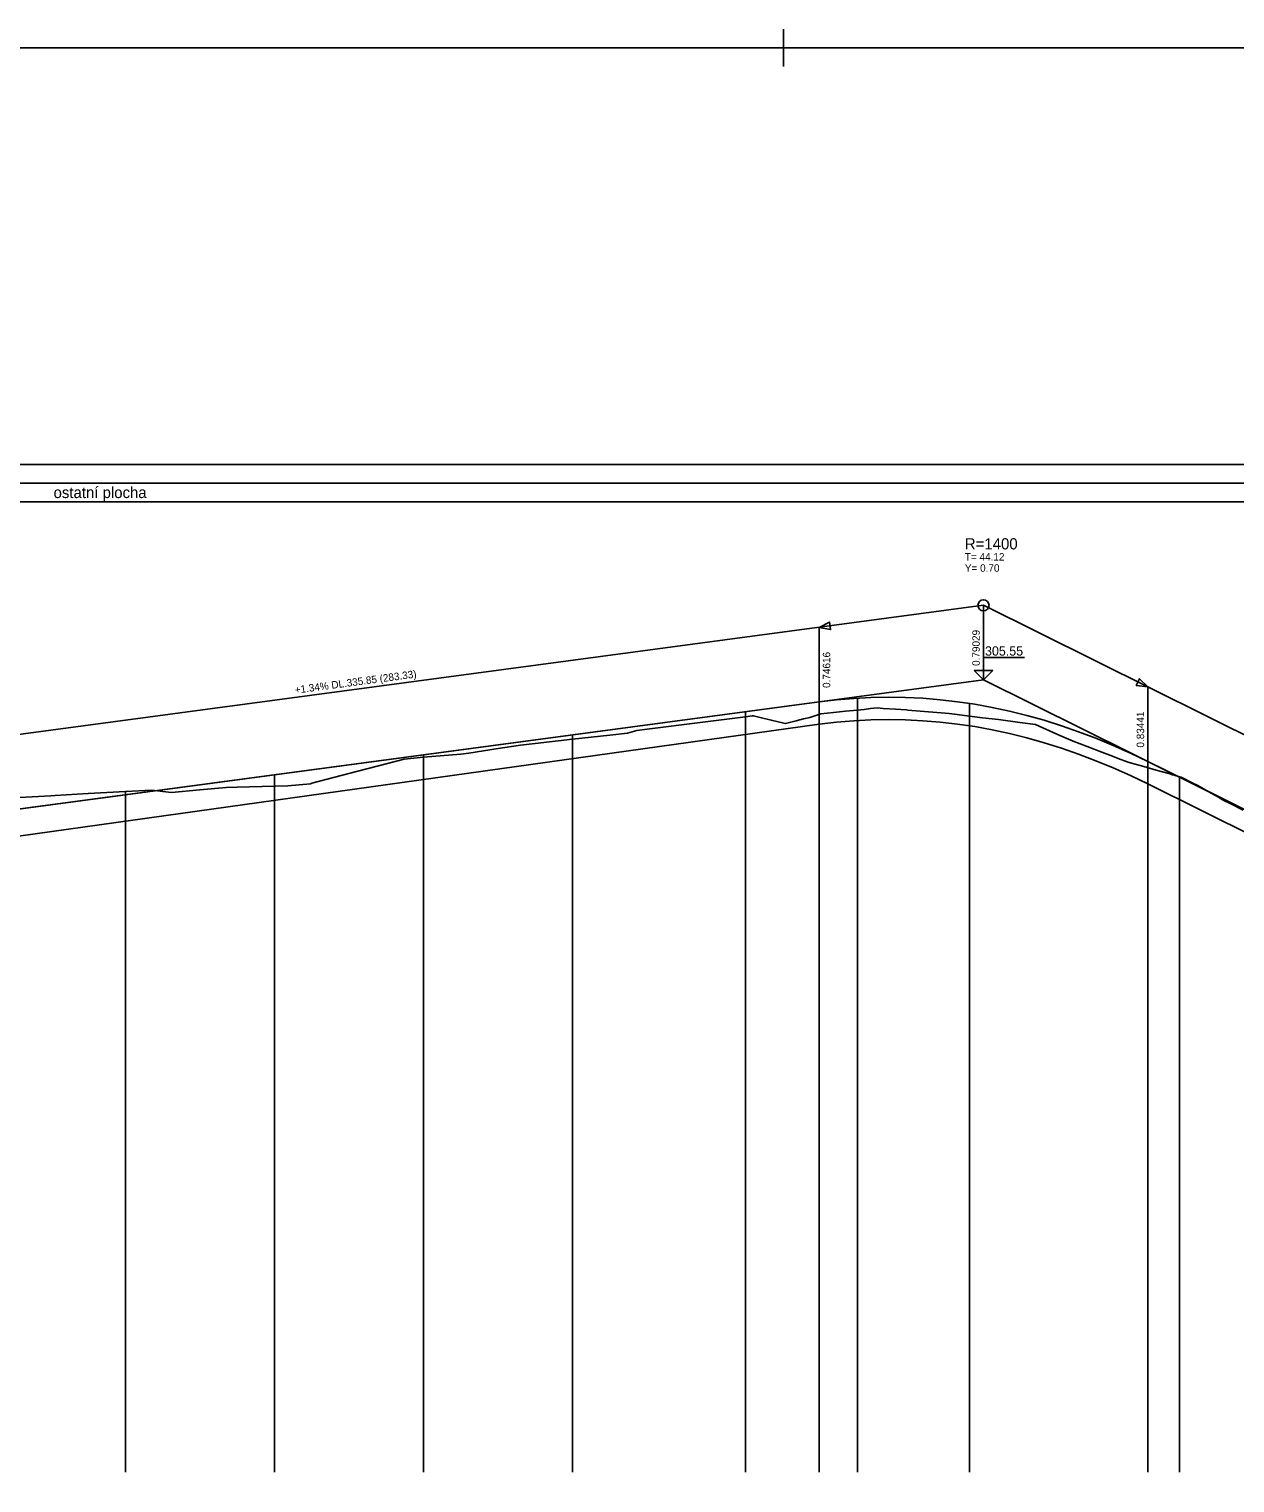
# Model space of a CAD drawing. Extents: x -39 to 1232, y -119 to 485.
# Drawn here: x 604.1 to 927.8, y 95.1 to 485.1 of the extents above; entities that cross this region are included whole.
import ezdxf

# ---------------------------------------------------------------- set-up
doc = ezdxf.new("R2010")
doc.units = 0
for name, color, linetype in [('KOTA', 7, 'Continuous'), ('NOVY_STAV', 7, 'Continuous'), ('NS_OBLOUK', 7, 'Continuous'), ('PRIKOPY', 7, 'Continuous'), ('ramecek', 7, 'Continuous'), ('REZY_PO', 7, 'Continuous'), ('SVK_STAT', 7, 'Continuous'), ('TABULKY', 7, 'Continuous')]:
    doc.layers.add(name, color=color, linetype=linetype)

msp = doc.modelspace()

# ---------------------------------------------------------------- linework, layer by layer
for p, q in [((806.58, 485.08), (806.58, 475.08)), ((806.58, 485.08), (806.58, 475.08)), ((806.58, 485.08), (806.58, 475.08)), ((806.58, 485.08), (806.58, 475.08)), ((806.58, 485.08), (806.58, 475.08)), ((806.58, 485.08), (806.58, 475.08)), ((806.58, 485.08), (806.58, 475.08)), ((806.58, 485.08), (806.58, 475.08)), ((806.58, 485.08), (806.58, 475.08)), ((806.58, 485.08), (806.58, 475.08)), ((806.58, 485.08), (806.58, 475.08)), ((806.58, 485.08), (806.58, 475.08)), ((806.58, 485.08), (806.58, 475.08)), ((806.58, 485.08), (806.58, 475.08)), ((806.58, 485.08), (806.58, 475.08)), ((806.58, 485.08), (806.58, 475.08)), ((806.58, 485.08), (806.58, 475.08)), ((806.58, 485.08), (806.58, 475.08)), ((806.58, 485.08), (806.58, 475.08)), ((806.58, 485.08), (806.58, 475.08)), ((806.58, 485.08), (806.58, 475.08)), ((806.58, 485.08), (806.58, 475.08)), ((806.58, 485.08), (806.58, 475.08)), ((806.58, 485.08), (806.58, 475.08)), ((806.58, 485.08), (806.58, 475.08)), ((806.58, 485.08), (806.58, 475.08)), ((806.58, 485.08), (806.58, 475.08)), ((806.58, 485.08), (806.58, 475.08)), ((806.58, 485.08), (806.58, 475.08)), ((806.58, 485.08), (806.58, 475.08)), ((806.58, 485.08), (806.58, 475.08)), ((806.58, 485.08), (806.58, 475.08)), ((806.58, 485.08), (806.58, 475.08)), ((806.58, 485.08), (806.58, 475.08)), ((806.58, 485.08), (806.58, 475.08)), ((806.58, 485.08), (806.58, 475.08)), ((806.58, 485.08), (806.58, 475.08)), ((806.58, 485.08), (806.58, 475.08)), ((806.58, 485.08), (806.58, 475.08)), ((806.58, 485.08), (806.58, 475.08)), ((811.58, 480.08), (801.58, 480.08)), ((811.58, 480.08), (801.58, 480.08)), ((811.58, 480.08), (801.58, 480.08)), ((811.58, 480.08), (801.58, 480.08)), ((811.58, 480.08), (801.58, 480.08)), ((811.58, 480.08), (801.58, 480.08)), ((811.58, 480.08), (801.58, 480.08)), ((811.58, 480.08), (801.58, 480.08)), ((811.58, 480.08), (801.58, 480.08)), ((811.58, 480.08), (801.58, 480.08)), ((811.58, 480.08), (801.58, 480.08)), ((811.58, 480.08), (801.58, 480.08)), ((811.58, 480.08), (801.58, 480.08)), ((811.58, 480.08), (801.58, 480.08)), ((811.58, 480.08), (801.58, 480.08)), ((811.58, 480.08), (801.58, 480.08)), ((811.58, 480.08), (801.58, 480.08)), ((811.58, 480.08), (801.58, 480.08)), ((811.58, 480.08), (801.58, 480.08)), ((811.58, 480.08), (801.58, 480.08)), ((811.58, 480.08), (801.58, 480.08)), ((811.58, 480.08), (801.58, 480.08)), ((811.58, 480.08), (801.58, 480.08)), ((811.58, 480.08), (801.58, 480.08)), ((811.58, 480.08), (801.58, 480.08)), ((811.58, 480.08), (801.58, 480.08)), ((811.58, 480.08), (801.58, 480.08)), ((811.58, 480.08), (801.58, 480.08)), ((811.58, 480.08), (801.58, 480.08)), ((811.58, 480.08), (801.58, 480.08)), ((811.58, 480.08), (801.58, 480.08)), ((811.58, 480.08), (801.58, 480.08)), ((811.58, 480.08), (801.58, 480.08)), ((811.58, 480.08), (801.58, 480.08)), ((811.58, 480.08), (801.58, 480.08)), ((811.58, 480.08), (801.58, 480.08)), ((811.58, 480.08), (801.58, 480.08)), ((811.58, 480.08), (801.58, 480.08)), ((811.58, 480.08), (801.58, 480.08)), ((811.58, 480.08), (801.58, 480.08))]:
    msp.add_line(p, q)
at = {"layer": 'KOTA'}
for points in [[(860.29, 313), (857.79, 313), (860.29, 310.5), (860.29, 316.5), (871.29, 316.5)], [(860.29, 310.5), (860.29, 310.5), (862.79, 313), (860.29, 313)]]:
    msp.add_lwpolyline(points, dxfattribs=at)
at = {"layer": 'NOVY_STAV'}
for points in [[(524.44, 285.53), (860.29, 330.5)], [(860.29, 310.5), (860.29, 330.5)], [(860.29, 330.5), (1100.08, 211.45)], [(70, 134.27), (107.59, 137.61), (183, 191.13), (370.63, 277.59), (464.64, 307.71), (524.44, 265.53), (860.29, 310.5), (1100.08, 191.45), (1135.72, 163.43), (1165.19, 163.09)], [(532.83, 266.65), (816.16, 304.59), (820.81, 305.13), (825.45, 305.52), (830.1, 305.76), (834.74, 305.84), (839.39, 305.77), (844.03, 305.55), (848.67, 305.17), (853.32, 304.63), (857.96, 303.95), (862.61, 303.1), (867.25, 302.11), (871.9, 300.96), (876.54, 299.65), (881.19, 298.2), (885.83, 296.58), (890.48, 294.82), (895.12, 292.9), (899.76, 290.82), (904.41, 288.59), (1092.83, 195.05)]]:
    msp.add_lwpolyline(points, dxfattribs=at)
msp.add_circle((860.29, 330.5), 1.5, dxfattribs=at)
at = {"layer": 'NS_OBLOUK'}
for points in [[(816.16, 324.59), (819, 325.98), (819.27, 324), (816.16, 324.59)], [(816.16, 304.59), (816.16, 324.59)], [(904.41, 308.59), (902.17, 310.82), (901.28, 309.03), (904.41, 308.59)], [(904.41, 288.59), (904.41, 308.59)]]:
    msp.add_lwpolyline(points, dxfattribs=at)
at = {"layer": 'PRIKOPY'}
msp.add_lwpolyline([(550.01, 261.42), (816.16, 298.59), (820.81, 299.13), (825.45, 299.52), (830.1, 299.76), (834.74, 299.84), (839.39, 299.77), (844.03, 299.55), (848.67, 299.17), (853.32, 298.63), (857.96, 297.95), (862.61, 297.1), (867.25, 296.11), (871.9, 294.96), (876.54, 293.65), (881.19, 292.2), (885.83, 290.58), (890.48, 288.82), (895.12, 286.9), (899.76, 284.82), (904.41, 282.59), (1092.93, 189)], dxfattribs=at)
at = {"layer": 'ramecek'}
msp.add_lwpolyline([(-34.42, -113.92), (1226.58, -113.92), (1226.58, 480.08), (-34.42, 480.08)], close=True, dxfattribs=at)
at = {"layer": 'REZY_PO'}
msp.add_lwpolyline([(600, 278.88), (610, 279.43), (611.16, 279.5), (620, 279.99), (630, 280.54), (637.08, 280.94), (640, 280.57), (642.39, 280.26), (650, 280.99), (657.02, 281.67), (660, 281.74), (670, 281.98), (673.61, 282.07), (679.63, 282.65), (680, 282.75), (690, 285.37), (700, 287.99), (704.84, 289.26), (710, 289.72), (720, 290.61), (722.18, 290.81), (730, 292.06), (736.07, 293.02), (740, 293.46), (750, 294.58), (760, 295.7), (764.73, 296.22), (767.29, 296.88), (770, 297.24), (774.36, 297.82), (780, 298.53), (790, 299.8), (796.38, 300.61), (798.19, 300.83), (798.53, 300.87), (800, 300.51), (803.33, 299.7), (806.67, 298.88), (807.15, 298.76), (810, 299.49), (811.99, 300.01), (813.33, 300.34), (813.67, 300.42), (816.66, 301.35), (816.67, 301.35), (820, 301.71), (823.23, 302.06), (826.46, 302.41), (828.23, 302.59), (830, 302.78), (831.78, 302.96), (833.33, 302.86), (836.67, 302.63), (839.64, 302.44), (840, 302.4), (843.33, 302.11), (846.67, 301.82), (850, 301.53), (851.07, 301.45), (853.27, 301.17), (856.54, 300.77), (860, 300.35), (864.34, 299.83), (870, 299.09), (874.21, 298.54), (880, 295.96), (884.32, 294.03), (890, 291.88), (891.32, 291.38), (894.21, 290.28), (897.11, 289.16), (899.09, 288.39), (900, 288.15), (903.33, 287.24), (906.67, 286.3), (910, 285.34), (910.99, 285.05), (911.44, 284.92), (912.88, 284.5), (913.32, 284.37), (916.44, 282.82), (917.81, 282.12), (920, 280.9), (923.33, 278.99), (924.44, 278.34), (926.67, 277.24), (930, 275.54)], dxfattribs=at)
at = {"layer": 'SVK_STAT'}
for points in [[(816.16, 98), (816.16, 304.59)], [(826.46, 98), (826.46, 305.58)], [(796.38, 98), (796.38, 301.94)], [(856.54, 98), (856.54, 304.16)], [(750, 98), (750, 295.73)], [(710, 98), (710, 290.37)], [(670, 98), (670, 285.02)], [(904.41, 98), (904.41, 288.59)], [(912.88, 98), (912.88, 284.5)], [(630, 98), (630, 280.54)]]:
    msp.add_lwpolyline(points, dxfattribs=at)
at = {"layer": 'TABULKY'}
for points in [[(70, 358.27), (1165.19, 358.27), (1165.19, 368.27), (70, 368.27), (70, 358.27)], [(70, 363.27), (1165.19, 363.27)]]:
    msp.add_lwpolyline(points, dxfattribs=at)

# ---------------------------------------------------------------- texts
at = {"layer": 'KOTA'}
msp.add_text('305.55', height=2.5, dxfattribs=at).set_placement((860.7, 317))
at = {"layer": 'NOVY_STAV'}
for s, rotation, p in [(' 0.79029', 90, (859.29, 313.5)), ('+1.34% DL.335.85 (283.33)', 7.6264, (675.59, 306.78))]:
    msp.add_text(s, height=2, rotation=rotation, dxfattribs=at).set_placement(p)
at = {"layer": 'NS_OBLOUK'}
for s, height, p in [('R=1400', 3, (855.29, 345.5)), ('T= 44.12', 2, (855.29, 342.5)), ('Y= 0.70', 2, (855.29, 339.5))]:
    msp.add_text(s, height=height, dxfattribs=at).set_placement(p)
for s, p in [(' 0.74616', (819.16, 307.59)), (' 0.83441', (903.41, 291.59))]:
    msp.add_text(s, height=2, rotation=90, dxfattribs=at).set_placement(p)
at = {"layer": 'TABULKY'}
msp.add_text('ostatní plocha', height=3, dxfattribs=at).set_placement((610.71, 359.27))

doc.saveas('drawing.dxf')
